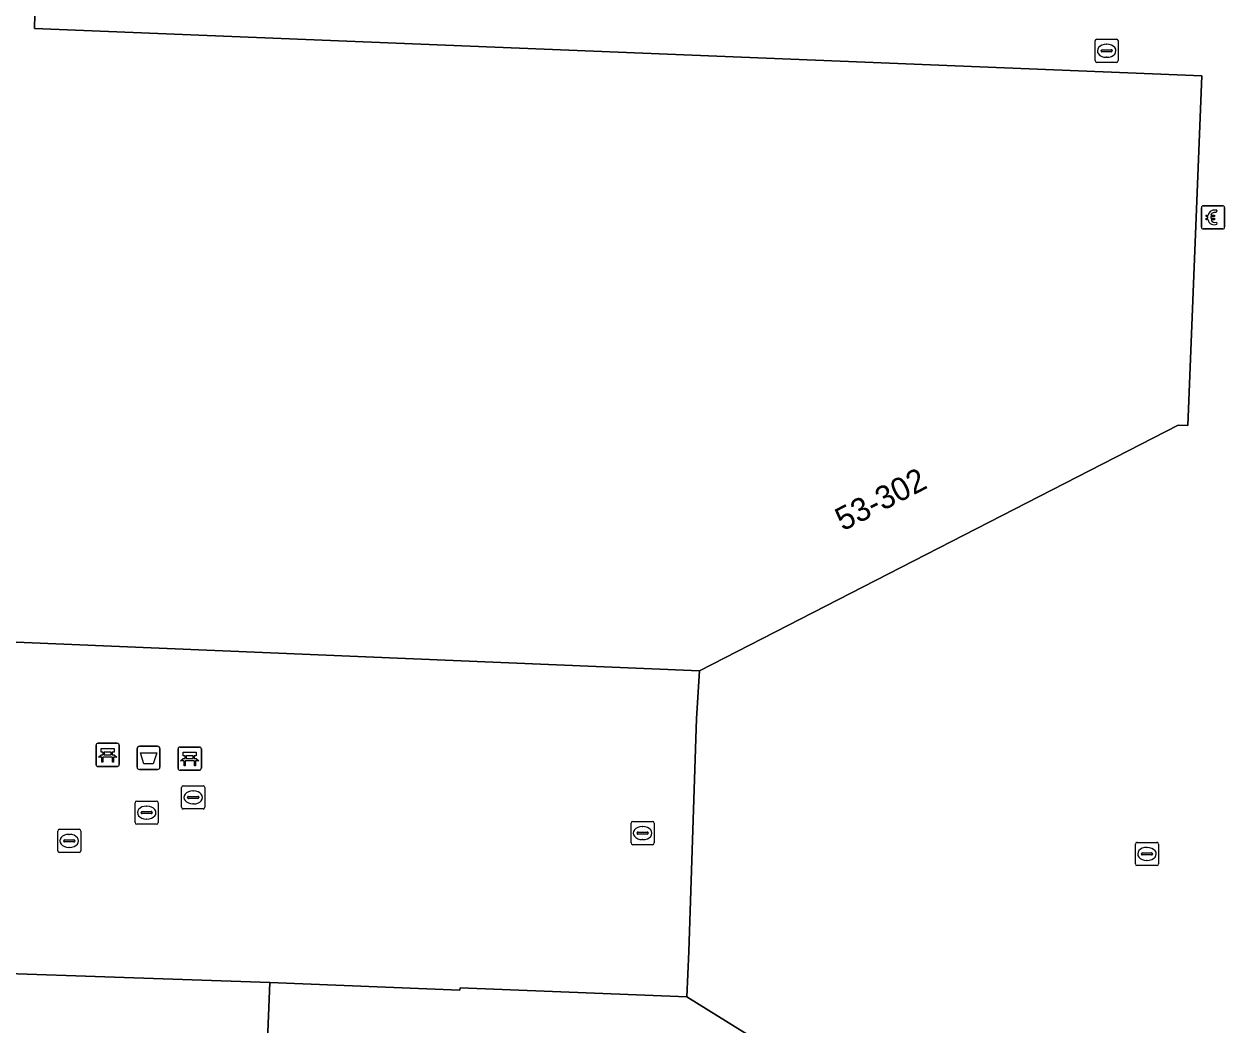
# Model space of a CAD drawing. Extents: x 160888 to 161385, y 386490 to 386908.
# Drawn here: x 161186.2 to 161238.1, y 386705.9 to 386749.1 of the extents above; entities that cross this region are included whole.
import ezdxf

# ---------------------------------------------------------------- set-up
doc = ezdxf.new("R2010")
doc.units = 0
for name, color, linetype in [('IMGEO_Afvalbak', 7, 'Continuous'), ('IMGEO_Bank', 7, 'Continuous'), ('IMGEO_Betaalautomaat', 7, 'Continuous'), ('IMGEO_Brandkraan', 7, 'Continuous'), ('IMGEO_Hek', 7, 'Continuous'), ('IMGEO_Kolk', 7, 'Continuous'), ('IMGEO_Pand', 7, 'Continuous'), ('IMGEO_Pand_nummerreeks', 7, 'Continuous'), ('IMGEO_Rioolput', 7, 'Continuous'), ('IMGEO_Voetgangersgebied_open', 7, 'Continuous')]:
    doc.layers.add(name, color=color, linetype=linetype)

msp = doc.modelspace()

# ---------------------------------------------------------------- linework, layer by layer
at = {"layer": 'IMGEO_Afvalbak'}
for p, q in [((161191.071, 386717.061), (161191.071, 386717.861)), ((161191.071, 386717.861), (161191.071, 386717.061)), ((161191.171, 386717.961), (161191.961, 386717.961)), ((161191.961, 386717.961), (161191.171, 386717.961)), ((161192.061, 386717.861), (161192.061, 386717.061)), ((161192.061, 386717.061), (161192.061, 386717.861)), ((161191.961, 386716.961), (161191.171, 386716.961)), ((161191.171, 386716.961), (161191.961, 386716.961))]:
    msp.add_line(p, q, dxfattribs=at)
msp.add_lwpolyline([(161191.214, 386717.675), (161191.918, 386717.675), (161191.769, 386717.205), (161191.363, 386717.205), (161191.214, 386717.675)], dxfattribs=at)
for centre, start, end in [((161191.171, 386717.861), 90, 180), ((161191.171, 386717.861), 90, 180), ((161191.961, 386717.861), 0, 90), ((161191.961, 386717.861), 360, 90), ((161191.171, 386717.061), 180, 270), ((161191.171, 386717.061), 180, 270), ((161191.961, 386717.061), 270, 0), ((161191.961, 386717.061), 270, 0)]:
    msp.add_arc(centre, 0.1, start, end, dxfattribs=at)
at = {"layer": 'IMGEO_Bank'}
for p, q in [((161189.304, 386717.165), (161189.304, 386718.006)), ((161189.304, 386718.006), (161189.304, 386717.165)), ((161189.379, 386718.09), (161190.22, 386718.09)), ((161190.22, 386718.09), (161189.379, 386718.09)), ((161189.613, 386717.596), (161189.613, 386717.702)), ((161189.657, 386717.702), (161189.657, 386717.596)), ((161189.945, 386717.708), (161189.663, 386717.708)), ((161189.951, 386717.596), (161189.951, 386717.702)), ((161189.995, 386717.702), (161189.995, 386717.596)), ((161190.304, 386718.015), (161190.304, 386717.174)), ((161190.304, 386717.174), (161190.304, 386718.015)), ((161192.844, 386717.003), (161192.844, 386717.844)), ((161192.844, 386717.844), (161192.844, 386717.003)), ((161192.919, 386717.928), (161193.76, 386717.928)), ((161193.76, 386717.928), (161192.919, 386717.928)), ((161193.844, 386717.853), (161193.844, 386717.012)), ((161193.844, 386717.012), (161193.844, 386717.853)), ((161190.001, 386717.488), (161189.608, 386717.488)), ((161189.663, 386717.59), (161189.945, 386717.59)), ((161193.541, 386717.326), (161193.148, 386717.326)), ((161193.153, 386717.434), (161193.153, 386717.54)), ((161193.197, 386717.54), (161193.197, 386717.434)), ((161193.485, 386717.546), (161193.203, 386717.546)), ((161193.203, 386717.428), (161193.485, 386717.428)), ((161193.491, 386717.434), (161193.491, 386717.54)), ((161193.535, 386717.54), (161193.535, 386717.434)), ((161190.229, 386717.09), (161189.388, 386717.09)), ((161189.388, 386717.09), (161190.229, 386717.09)), ((161193.769, 386716.928), (161192.928, 386716.928)), ((161192.928, 386716.928), (161193.769, 386716.928))]:
    msp.add_line(p, q, dxfattribs=at)
for points in [[(161189.607, 386717.708), (161189.521, 386717.708), (161189.521, 386717.869), (161190.084, 386717.869), (161190.084, 386717.708), (161190.001, 386717.708)], [(161193.147, 386717.546), (161193.061, 386717.546), (161193.061, 386717.707), (161193.624, 386717.707), (161193.624, 386717.546), (161193.541, 386717.546)], [(161189.551, 386717.488), (161189.409, 386717.488), (161189.521, 386717.59), (161189.607, 386717.59)], [(161189.601, 386717.481), (161189.601, 386717.274), (161189.558, 386717.274), (161189.558, 386717.481)], [(161190.001, 386717.59), (161190.084, 386717.59), (161190.196, 386717.488), (161190.057, 386717.488)], [(161190.051, 386717.481), (161190.051, 386717.274), (161190.007, 386717.274), (161190.007, 386717.481)], [(161193.091, 386717.326), (161192.949, 386717.326), (161193.061, 386717.428), (161193.147, 386717.428)], [(161193.141, 386717.319), (161193.141, 386717.112), (161193.098, 386717.112), (161193.098, 386717.319)], [(161193.541, 386717.428), (161193.624, 386717.428), (161193.736, 386717.326), (161193.597, 386717.326)], [(161193.591, 386717.319), (161193.591, 386717.112), (161193.547, 386717.112), (161193.547, 386717.319)]]:
    msp.add_lwpolyline(points, dxfattribs=at)
for centre, radius, start, end in [((161189.382, 386718.012), 0.0779, 92.4484, 184.2845), ((161189.382, 386718.012), 0.0779, 92.4484, 184.2845), ((161189.606, 386717.701), 0.00671, 2.8957, 87.1043), ((161189.663, 386717.701), 0.00671, 92.8957, 177.1043), ((161189.945, 386717.701), 0.00671, 2.8957, 87.1043), ((161190.002, 386717.701), 0.00671, 92.8957, 177.1043), ((161190.226, 386718.012), 0.0779, 2.4484, 94.2845), ((161190.226, 386718.012), 0.0779, 2.4484, 94.2845), ((161192.922, 386717.85), 0.0779, 92.4484, 184.2845), ((161192.922, 386717.85), 0.0779, 92.4484, 184.2845), ((161193.766, 386717.85), 0.0779, 2.4484, 94.2845), ((161193.766, 386717.85), 0.0779, 2.4484, 94.2845), ((161189.551, 386717.481), 0.00671, 2.8957, 87.1043), ((161189.608, 386717.481), 0.00671, 92.8957, 177.1043), ((161189.606, 386717.597), 0.00671, 272.8957, 357.1043), ((161189.663, 386717.597), 0.00671, 182.8957, 267.1043), ((161189.945, 386717.597), 0.00671, 272.8957, 357.1043), ((161190.002, 386717.597), 0.00671, 182.8957, 267.1043), ((161190, 386717.481), 0.00671, 2.8957, 87.1043), ((161190.057, 386717.481), 0.00671, 92.8957, 177.1043), ((161190.226, 386717.168), 0.0779, 272.4484, 4.2845), ((161190.226, 386717.168), 0.0779, 272.4484, 4.2845), ((161193.091, 386717.319), 0.00671, 2.8957, 87.1043), ((161193.148, 386717.319), 0.00671, 92.8957, 177.1043), ((161193.146, 386717.539), 0.00671, 2.8957, 87.1043), ((161193.146, 386717.435), 0.00671, 272.8957, 357.1043), ((161193.203, 386717.539), 0.00671, 92.8957, 177.1043), ((161193.203, 386717.435), 0.00671, 182.8957, 267.1043), ((161193.485, 386717.539), 0.00671, 2.8957, 87.1043), ((161193.485, 386717.435), 0.00671, 272.8957, 357.1043), ((161193.542, 386717.539), 0.00671, 92.8957, 177.1043), ((161193.542, 386717.435), 0.00671, 182.8957, 267.1043), ((161193.54, 386717.319), 0.00671, 2.8957, 87.1043), ((161193.597, 386717.319), 0.00671, 92.8957, 177.1043), ((161189.382, 386717.168), 0.0779, 182.4484, 274.2845), ((161189.382, 386717.168), 0.0779, 182.4484, 274.2845), ((161192.922, 386717.006), 0.0779, 182.4484, 274.2845), ((161192.922, 386717.006), 0.0779, 182.4484, 274.2845), ((161193.766, 386717.006), 0.0779, 272.4484, 4.2845), ((161193.766, 386717.006), 0.0779, 272.4484, 4.2845)]:
    msp.add_arc(centre, radius, start, end, dxfattribs=at)
at = {"layer": 'IMGEO_Betaalautomaat'}
for p, q in [((161236.966, 386740.342), (161236.966, 386741.183)), ((161236.966, 386741.183), (161236.966, 386740.342)), ((161237.041, 386741.266), (161237.882, 386741.266)), ((161237.882, 386741.266), (161237.041, 386741.266)), ((161237.628, 386741.071), (161237.611, 386740.971)), ((161237.965, 386741.192), (161237.965, 386740.351)), ((161237.965, 386740.351), (161237.965, 386741.192)), ((161237.249, 386740.73), (161237.249, 386740.798)), ((161237.37, 386740.798), (161237.37, 386740.73)), ((161237.615, 386740.565), (161237.637, 386740.478)), ((161237.891, 386740.267), (161237.05, 386740.267)), ((161237.05, 386740.267), (161237.891, 386740.267))]:
    msp.add_line(p, q, dxfattribs=at)
for points in [[(161237.249, 386740.798), (161237.18, 386740.798), (161237.18, 386740.867), (161237.259, 386740.867)], [(161237.254, 386740.661), (161237.18, 386740.661), (161237.18, 386740.73), (161237.249, 386740.73)], [(161237.381, 386740.867), (161237.528, 386740.867), (161237.528, 386740.798), (161237.37, 386740.798)], [(161237.37, 386740.73), (161237.528, 386740.73), (161237.528, 386740.661), (161237.384, 386740.661)]]:
    msp.add_lwpolyline(points, dxfattribs=at)
for centre, radius, start, end in [((161237.044, 386741.189), 0.0779, 92.4484, 184.2845), ((161237.044, 386741.189), 0.0779, 92.4484, 184.2845), ((161237.542, 386740.791), 0.293, 73.014, 165.0139), ((161237.888, 386741.189), 0.0779, 2.4484, 94.2845), ((161237.888, 386741.189), 0.0779, 2.4484, 94.2845), ((161237.515, 386740.716), 0.267, 191.8096, 297.0389), ((161237.548, 386740.804), 0.179, 69.3236, 159.5683), ((161237.548, 386740.731), 0.179, 202.7625, 291.8693), ((161237.044, 386740.345), 0.0779, 182.4484, 274.2845), ((161237.044, 386740.345), 0.0779, 182.4484, 274.2845), ((161237.888, 386740.345), 0.0779, 272.4484, 4.2845), ((161237.888, 386740.345), 0.0779, 272.4484, 4.2845)]:
    msp.add_arc(centre, radius, start, end, dxfattribs=at)
at = {"layer": 'IMGEO_Brandkraan'}
for p, q in [((161187.649, 386713.454), (161187.649, 386714.306)), ((161187.724, 386714.38), (161188.576, 386714.38)), ((161188.137, 386714.16), (161188.162, 386714.16)), ((161188.65, 386714.306), (161188.65, 386713.454)), ((161187.908, 386713.874), (161187.908, 386713.886)), ((161188.346, 386713.837), (161187.948, 386713.837)), ((161187.951, 386713.923), (161188.349, 386713.923)), ((161188.16, 386713.6), (161188.135, 386713.6)), ((161188.392, 386713.886), (161188.392, 386713.874)), ((161188.576, 386713.38), (161187.724, 386713.38))]:
    msp.add_line(p, q, dxfattribs=at)
for points in [[(161187.649, 386713.454), (161187.649, 386714.306)], [(161187.724, 386714.38), (161188.576, 386714.38)], [(161188.65, 386714.306), (161188.65, 386713.454)], [(161188.576, 386713.38), (161187.724, 386713.38)]]:
    msp.add_lwpolyline(points, dxfattribs=at)
for centre, radius, start, end in [((161187.726, 386714.304), 0.0765, 91.552, 178.448), ((161187.726, 386714.304), 0.0765, 91.552, 178.448), ((161188.574, 386714.304), 0.0765, 1.552, 88.448), ((161188.574, 386714.304), 0.0765, 1.552, 88.448), ((161187.948, 386713.883), 0.0403, 85.8775, 175.7526), ((161187.945, 386713.873), 0.0366, 178.938, 274.7102), ((161188.349, 386713.88), 0.043, 264.8664, 352.4533), ((161188.353, 386713.885), 0.0386, 1.7309, 96.639), ((161187.726, 386713.456), 0.0765, 181.552, 268.448), ((161187.726, 386713.456), 0.0765, 181.552, 268.448), ((161188.574, 386713.456), 0.0765, 271.552, 358.448), ((161188.574, 386713.456), 0.0765, 271.552, 358.448)]:
    msp.add_arc(centre, radius, start, end, dxfattribs=at)
for centre, major_axis, ratio, start_param, end_param in [((161188.136, 386713.88), (-0.387, 0.002), 0.722429, 4.712389, 7.853982), ((161188.161, 386713.88), (-0.39, 0.002), 0.717154, 1.570796, 4.712389)]:
    msp.add_ellipse(centre, major_axis=major_axis, ratio=ratio, start_param=start_param, end_param=end_param, dxfattribs=at)
at = {"layer": 'IMGEO_Hek'}
for points in [[(161215.329, 386721.218), (161215.194, 386719.154)], [(161215.194, 386719.154), (161214.868, 386709.114)], [(161214.868, 386709.114), (161214.777, 386707.152)]]:
    msp.add_lwpolyline(points, dxfattribs=at)
at = {"layer": 'IMGEO_Kolk'}
for p, q in [((161232.382, 386747.523), (161232.382, 386748.375)), ((161232.457, 386748.449), (161233.309, 386748.449)), ((161233.383, 386748.375), (161233.383, 386747.523)), ((161232.641, 386747.943), (161232.641, 386747.955)), ((161233.079, 386747.906), (161232.681, 386747.906)), ((161232.684, 386747.992), (161233.082, 386747.992)), ((161232.87, 386748.229), (161232.895, 386748.229)), ((161233.125, 386747.955), (161233.125, 386747.943)), ((161233.309, 386747.449), (161232.457, 386747.449)), ((161232.893, 386747.669), (161232.868, 386747.669)), ((161190.987, 386714.673), (161190.987, 386715.525)), ((161191.062, 386715.599), (161191.914, 386715.599)), ((161191.246, 386715.093), (161191.246, 386715.105)), ((161191.289, 386715.142), (161191.687, 386715.142)), ((161191.475, 386715.379), (161191.5, 386715.379)), ((161191.73, 386715.105), (161191.73, 386715.093)), ((161191.988, 386715.525), (161191.988, 386714.673)), ((161191.914, 386714.599), (161191.062, 386714.599)), ((161191.684, 386715.056), (161191.286, 386715.056)), ((161191.498, 386714.819), (161191.473, 386714.819)), ((161212.372, 386713.791), (161212.372, 386714.643)), ((161212.447, 386714.717), (161213.299, 386714.717)), ((161213.373, 386714.643), (161213.373, 386713.791)), ((161212.631, 386714.211), (161212.631, 386714.223)), ((161213.069, 386714.174), (161212.671, 386714.174)), ((161212.674, 386714.26), (161213.072, 386714.26)), ((161212.86, 386714.497), (161212.885, 386714.497)), ((161213.115, 386714.223), (161213.115, 386714.211)), ((161213.299, 386713.717), (161212.447, 386713.717)), ((161212.883, 386713.937), (161212.858, 386713.937)), ((161234.121, 386712.892), (161234.121, 386713.744)), ((161234.196, 386713.818), (161235.048, 386713.818)), ((161234.609, 386713.598), (161234.634, 386713.598)), ((161235.122, 386713.744), (161235.122, 386712.892)), ((161234.38, 386713.312), (161234.38, 386713.324)), ((161234.818, 386713.275), (161234.42, 386713.275)), ((161234.423, 386713.361), (161234.821, 386713.361)), ((161234.632, 386713.038), (161234.607, 386713.038)), ((161234.864, 386713.324), (161234.864, 386713.312)), ((161235.048, 386712.818), (161234.196, 386712.818))]:
    msp.add_line(p, q, dxfattribs=at)
for points in [[(161232.382, 386747.523), (161232.382, 386748.375)], [(161232.457, 386748.449), (161233.309, 386748.449)], [(161233.383, 386748.375), (161233.383, 386747.523)], [(161233.309, 386747.449), (161232.457, 386747.449)], [(161190.987, 386714.673), (161190.987, 386715.525)], [(161191.062, 386715.599), (161191.914, 386715.599)], [(161191.988, 386715.525), (161191.988, 386714.673)], [(161191.914, 386714.599), (161191.062, 386714.599)], [(161212.372, 386713.791), (161212.372, 386714.643)], [(161212.447, 386714.717), (161213.299, 386714.717)], [(161213.373, 386714.643), (161213.373, 386713.791)], [(161213.299, 386713.717), (161212.447, 386713.717)], [(161234.121, 386712.892), (161234.121, 386713.744)], [(161234.196, 386713.818), (161235.048, 386713.818)], [(161235.122, 386713.744), (161235.122, 386712.892)], [(161235.048, 386712.818), (161234.196, 386712.818)]]:
    msp.add_lwpolyline(points, dxfattribs=at)
for centre, radius, start, end in [((161232.459, 386748.373), 0.0765, 91.552, 178.448), ((161232.459, 386748.373), 0.0765, 91.552, 178.448), ((161233.307, 386748.373), 0.0765, 1.552, 88.448), ((161233.307, 386748.373), 0.0765, 1.552, 88.448), ((161232.681, 386747.952), 0.0403, 85.8775, 175.7526), ((161232.678, 386747.942), 0.0366, 178.938, 274.7102), ((161233.082, 386747.949), 0.043, 264.8664, 352.4533), ((161233.086, 386747.954), 0.0386, 1.7309, 96.639), ((161232.459, 386747.525), 0.0765, 181.552, 268.448), ((161232.459, 386747.525), 0.0765, 181.552, 268.448), ((161233.307, 386747.525), 0.0765, 271.552, 358.448), ((161233.307, 386747.525), 0.0765, 271.552, 358.448), ((161191.064, 386715.523), 0.0765, 91.552, 178.448), ((161191.064, 386715.523), 0.0765, 91.552, 178.448), ((161191.286, 386715.102), 0.0403, 85.8775, 175.7526), ((161191.283, 386715.092), 0.0366, 178.938, 274.7102), ((161191.687, 386715.099), 0.043, 264.8664, 352.4533), ((161191.691, 386715.104), 0.0386, 1.7309, 96.639), ((161191.912, 386715.523), 0.0765, 1.552, 88.448), ((161191.912, 386715.523), 0.0765, 1.552, 88.448), ((161191.064, 386714.675), 0.0765, 181.552, 268.448), ((161191.064, 386714.675), 0.0765, 181.552, 268.448), ((161191.912, 386714.675), 0.0765, 271.552, 358.448), ((161191.912, 386714.675), 0.0765, 271.552, 358.448), ((161212.449, 386714.641), 0.0765, 91.552, 178.448), ((161212.449, 386714.641), 0.0765, 91.552, 178.448), ((161213.297, 386714.641), 0.0765, 1.552, 88.448), ((161213.297, 386714.641), 0.0765, 1.552, 88.448), ((161212.671, 386714.22), 0.0403, 85.8775, 175.7526), ((161212.668, 386714.21), 0.0366, 178.938, 274.7102), ((161213.072, 386714.217), 0.043, 264.8664, 352.4533), ((161213.076, 386714.222), 0.0386, 1.7309, 96.639), ((161212.449, 386713.793), 0.0765, 181.552, 268.448), ((161212.449, 386713.793), 0.0765, 181.552, 268.448), ((161213.297, 386713.793), 0.0765, 271.552, 358.448), ((161213.297, 386713.793), 0.0765, 271.552, 358.448), ((161234.198, 386713.742), 0.0765, 91.552, 178.448), ((161234.198, 386713.742), 0.0765, 91.552, 178.448), ((161235.046, 386713.742), 0.0765, 1.552, 88.448), ((161235.046, 386713.742), 0.0765, 1.552, 88.448), ((161234.42, 386713.321), 0.0403, 85.8775, 175.7526), ((161234.417, 386713.311), 0.0366, 178.938, 274.7102), ((161234.821, 386713.318), 0.043, 264.8664, 352.4533), ((161234.825, 386713.323), 0.0386, 1.7309, 96.639), ((161234.198, 386712.894), 0.0765, 181.552, 268.448), ((161234.198, 386712.894), 0.0765, 181.552, 268.448), ((161235.046, 386712.894), 0.0765, 271.552, 358.448), ((161235.046, 386712.894), 0.0765, 271.552, 358.448)]:
    msp.add_arc(centre, radius, start, end, dxfattribs=at)
for centre, major_axis, ratio, start_param, end_param in [((161232.869, 386747.949), (-0.387, 0.002), 0.722429, 4.712389, 7.853982), ((161232.894, 386747.949), (-0.39, 0.002), 0.717154, 1.570796, 4.712389), ((161191.474, 386715.099), (-0.387, 0.002), 0.722429, 4.712389, 7.853982), ((161191.499, 386715.099), (-0.39, 0.002), 0.717154, 1.570796, 4.712389), ((161212.859, 386714.217), (-0.387, 0.002), 0.722429, 4.712389, 7.853982), ((161212.884, 386714.217), (-0.39, 0.002), 0.717154, 1.570796, 4.712389), ((161234.608, 386713.318), (-0.387, 0.002), 0.722429, 4.712389, 7.853982), ((161234.633, 386713.318), (-0.39, 0.002), 0.717154, 1.570796, 4.712389)]:
    msp.add_ellipse(centre, major_axis=major_axis, ratio=ratio, start_param=start_param, end_param=end_param, dxfattribs=at)
at = {"layer": 'IMGEO_Pand'}
msp.add_lwpolyline([(161173.519, 386722.968), (161215.329, 386721.218), (161235.961, 386731.803), (161236.376, 386731.786), (161236.989, 386746.871), (161186.65, 386748.905), (161186.656, 386749.048), (161186.694, 386750), (161186.852, 386753.913), (161187.146, 386761.187), (161187.434, 386768.304), (161188.011, 386782.569), (161188.797, 386802.008), (161189.282, 386814.008), (161189.471, 386818.672), (161189.65, 386820.828), (161199.13, 386820.44), (161199.621, 386832.448), (161199.627, 386832.585), (161190.117, 386832.93), (161170.867, 386833.628)], dxfattribs=at)
msp.add_lwpolyline([(161234.482, 386694.929), (161214.777, 386707.152), (161205, 386707.543), (161204.996, 386707.443), (161196.801, 386707.775), (161194.42, 386648.752), (161194.32, 386648.757), (161194.302, 386648.347), (161216.005, 386647.458), (161217.32, 386680.124), (161234.274, 386679.434), (161234.896, 386694.91)], close=True, dxfattribs=at)
at = {"layer": 'IMGEO_Rioolput'}
for p, q in [((161192.992, 386715.33), (161192.992, 386716.182)), ((161193.067, 386716.256), (161193.919, 386716.256)), ((161193.993, 386716.182), (161193.993, 386715.33)), ((161193.251, 386715.75), (161193.251, 386715.762)), ((161193.689, 386715.713), (161193.291, 386715.713)), ((161193.294, 386715.799), (161193.692, 386715.799)), ((161193.48, 386716.036), (161193.505, 386716.036)), ((161193.735, 386715.762), (161193.735, 386715.75)), ((161193.919, 386715.256), (161193.067, 386715.256)), ((161193.503, 386715.476), (161193.478, 386715.476))]:
    msp.add_line(p, q, dxfattribs=at)
for points in [[(161192.992, 386715.33), (161192.992, 386716.182)], [(161193.067, 386716.256), (161193.919, 386716.256)], [(161193.993, 386716.182), (161193.993, 386715.33)], [(161193.919, 386715.256), (161193.067, 386715.256)]]:
    msp.add_lwpolyline(points, dxfattribs=at)
for centre, radius, start, end in [((161193.069, 386716.18), 0.0765, 91.552, 178.448), ((161193.069, 386716.18), 0.0765, 91.552, 178.448), ((161193.917, 386716.18), 0.0765, 1.552, 88.448), ((161193.917, 386716.18), 0.0765, 1.552, 88.448), ((161193.291, 386715.759), 0.0403, 85.8775, 175.7526), ((161193.288, 386715.749), 0.0366, 178.938, 274.7102), ((161193.692, 386715.756), 0.043, 264.8664, 352.4533), ((161193.696, 386715.761), 0.0386, 1.7309, 96.639), ((161193.069, 386715.332), 0.0765, 181.552, 268.448), ((161193.069, 386715.332), 0.0765, 181.552, 268.448), ((161193.917, 386715.332), 0.0765, 271.552, 358.448), ((161193.917, 386715.332), 0.0765, 271.552, 358.448)]:
    msp.add_arc(centre, radius, start, end, dxfattribs=at)
for centre, major_axis, ratio, start_param, end_param in [((161193.479, 386715.756), (-0.387, 0.002), 0.722429, 4.712389, 7.853982), ((161193.504, 386715.756), (-0.39, 0.002), 0.717154, 1.570796, 4.712389)]:
    msp.add_ellipse(centre, major_axis=major_axis, ratio=ratio, start_param=start_param, end_param=end_param, dxfattribs=at)
at = {"layer": 'IMGEO_Voetgangersgebied_open'}
for points in [[(161267.035, 386750.03), (161265.767, 386750.053), (161265.005, 386750.043), (161218.231, 386752.088), (161189.757, 386753.134), (161187.146, 386761.187), (161186.852, 386753.913), (161186.694, 386750), (161186.656, 386749.048), (161186.65, 386748.905), (161236.989, 386746.871), (161236.376, 386731.786), (161235.961, 386731.803), (161215.329, 386721.218), (161215.194, 386719.154), (161214.868, 386709.114), (161214.777, 386707.152), (161234.482, 386694.929), (161234.896, 386694.91), (161234.274, 386679.434), (161217.32, 386680.124), (161216.005, 386647.458), (161219.091, 386647.411), (161219.977, 386669.302)], [(161137.065, 386712.159), (161147.892, 386711.738), (161147.81, 386709.63), (161153.396, 386709.393), (161178.374, 386708.407), (161196.801, 386707.775), (161204.996, 386707.443), (161205, 386707.543), (161214.777, 386707.152), (161214.868, 386709.114), (161215.194, 386719.154), (161215.329, 386721.218), (161173.519, 386722.968), (161170.948, 386723.087), (161164.179, 386723.4), (161161.551, 386723.521), (161138.885, 386724.445)], [(161194.42, 386648.752), (161196.801, 386707.775), (161178.374, 386708.407), (161179.554, 386708.28), (161180.718, 386707.986), (161181.822, 386707.521), (161183.781, 386706.174), (161184.602, 386705.296)]]:
    msp.add_lwpolyline(points, dxfattribs=at)

# ---------------------------------------------------------------- texts
at = {"layer": 'IMGEO_Pand_nummerreeks'}
msp.add_text('53-302', height=1, rotation=27.1582, dxfattribs=at).set_placement((161221.509, 386727.221))

doc.saveas('drawing.dxf')
